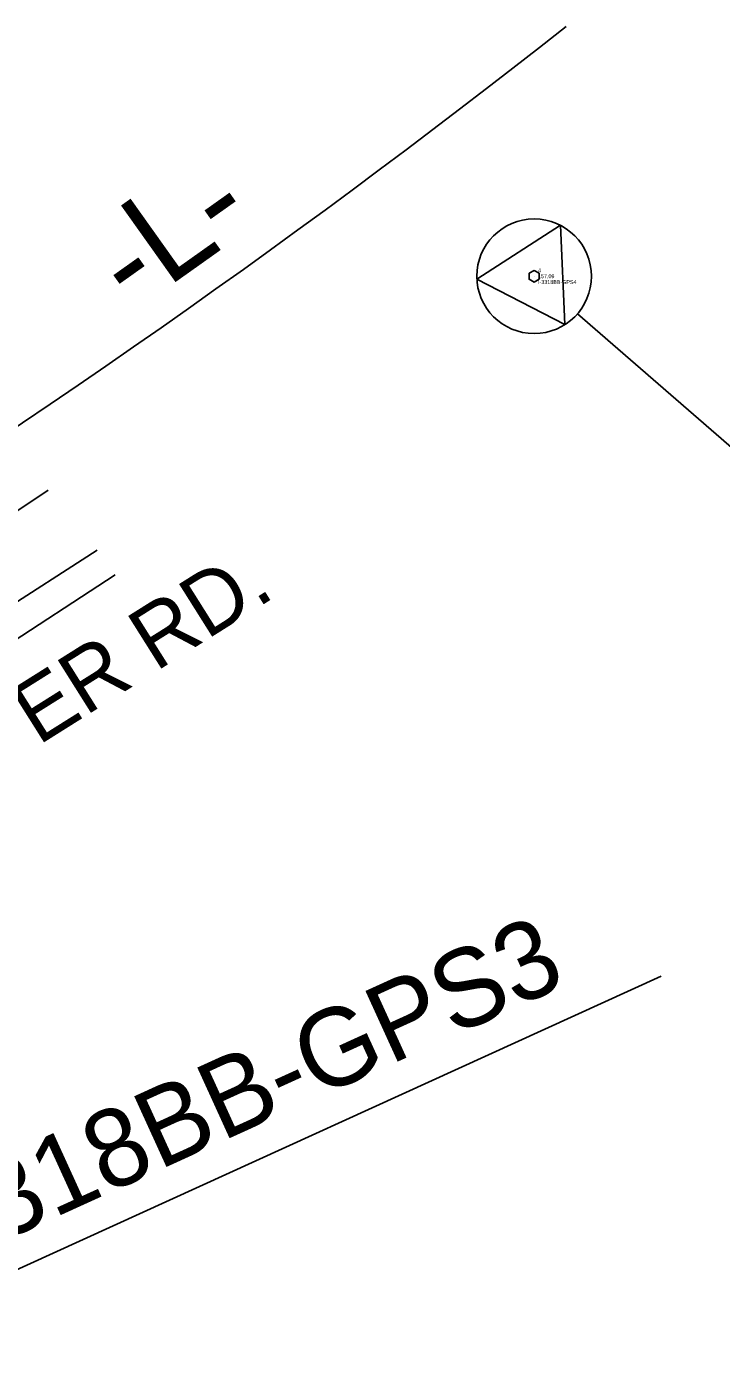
# Model space of a CAD drawing. Extents: x 2243531 to 2252747, y 658714 to 667210.
# Drawn here: x 2250626 to 2251073, y 663611 to 664465 of the extents above; entities that cross this region are included whole.
import ezdxf

# ---------------------------------------------------------------- set-up
doc = ezdxf.new("R2010")
doc.units = 0
for name, color, linetype in [('CTL GPS Vertical CELL', 7, 'Continuous'), ('CTL GPS Vertical Cogo Comment', 7, 'Continuous'), ('CTL GPS Vertical Cogo Elevation', 7, 'Continuous'), ('CTL GPS Vertical Cogo Number', 7, 'Continuous'), ('CTL NGS Horizontal CELL', 7, 'Continuous'), ('CTL Supplemental Horizontal and Vertical Text', 7, 'Continuous'), ('Exist Roads EOP', 7, 'Continuous'), ('Exist Roads EOP Text', 7, 'Continuous'), ('Prop Horizontal Alignment', 7, 'Continuous'), ('Prop Horizontal Alignment Direction Label', 7, 'Continuous')]:
    doc.layers.add(name, color=color, linetype=linetype)

msp = doc.modelspace()

# ---------------------------------------------------------------- linework, layer by layer
at = {"layer": 'CTL GPS Vertical CELL'}
msp.add_line((2250952.43, 664304.48), (2250952.43, 664304.48), dxfattribs=at)
msp.add_lwpolyline([(2250949.2, 664306.35), (2250952.45, 664308.17), (2250955.7, 664306.38), (2250955.65, 664302.65), (2250952.4, 664300.77), (2250949.2, 664302.58)], close=True, dxfattribs=at)
at = {"layer": 'CTL NGS Horizontal CELL'}
for p, q in [((2250952.43, 664304.48), (2250952.43, 664304.48)), ((2250980.25, 664280.29), (2251155.5, 664127.89)), ((2250501.32, 663611.07), (2251034.19, 663853.89))]:
    msp.add_line(p, q, dxfattribs=at)
msp.add_lwpolyline([(2250915.56, 664302.55), (2250972.21, 664273.31), (2250969.34, 664337.25), (2250915.56, 664302.55)], dxfattribs=at)
msp.add_circle((2250952.43, 664304.48), 36.87, dxfattribs=at)
at = {"layer": 'Exist Roads EOP'}
for p, q in [((2250538.42, 664099.52), (2250639.73, 664166.68)), ((2250591.62, 664076.77), (2250671.26, 664128.23)), ((2250602.62, 664059.87), (2250682.84, 664112.38))]:
    msp.add_line(p, q, dxfattribs=at)
at = {"layer": 'Prop Horizontal Alignment'}
msp.add_arc((2247423.42, 668962.88), 5729.58, 294.43013, 308.28013, dxfattribs=at)

# ---------------------------------------------------------------- texts
at = {"layer": 'CTL GPS Vertical Cogo Comment'}
msp.add_text('I-3318BB-GPS4', height=2.5, dxfattribs=at).set_placement((2250954.93, 664299.48))
at = {"layer": 'CTL GPS Vertical Cogo Elevation'}
msp.add_text('157.09', height=2.5, dxfattribs=at).set_placement((2250954.93, 664303.23))
at = {"layer": 'CTL GPS Vertical Cogo Number'}
msp.add_text('4', height=2.5, dxfattribs=at).set_placement((2250954.93, 664306.98))
at = {"layer": 'CTL Supplemental Horizontal and Vertical Text'}
msp.add_text('I-3318BB-GPS3', height=49.9994, rotation=24.49794, dxfattribs=at).set_placement((2250538.4, 663650.24))
at = {"layer": 'Exist Roads EOP Text'}
msp.add_text('OLD RIVER RD.', height=39.9995, rotation=32.17378, dxfattribs=at).set_placement((2250452.28, 663888.16))
at = {"layer": 'Prop Horizontal Alignment Direction Label'}
msp.add_text('-L-', height=60.479, rotation=35.40038, dxfattribs=at).set_placement((2250694.36, 664281.27))

doc.saveas('drawing.dxf')
